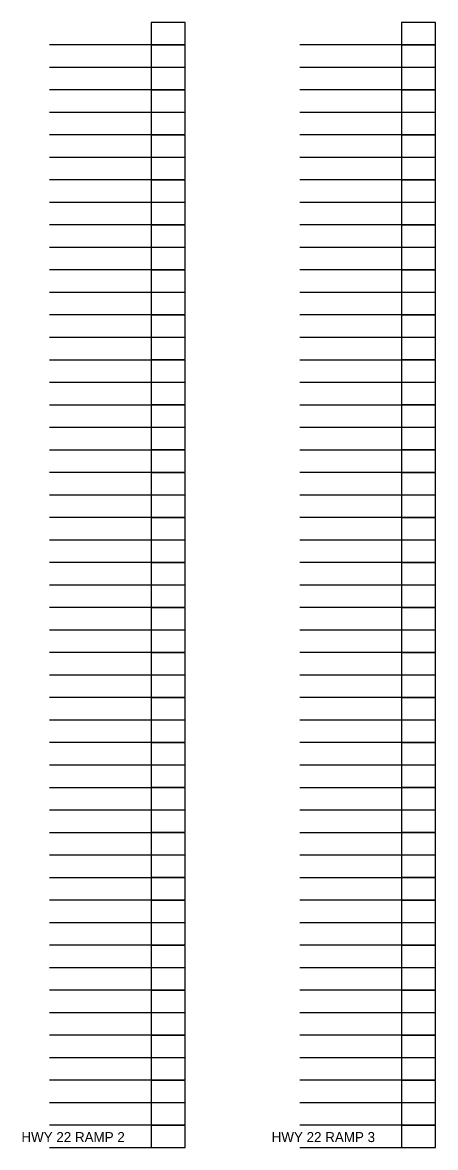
# Model space of a CAD drawing. Extents: x 625451 to 4181825, y 337941 to 441164.
# Drawn here: x 678612 to 686863, y 373673 to 396164 of the extents above; entities that cross this region are included whole.
import ezdxf

# ---------------------------------------------------------------- set-up
doc = ezdxf.new("R2010")
doc.units = 0
for name, color, linetype in [('PLOT_BDR-NOTUSED', 7, 'Continuous'), ('R_CX_LAYOUT-HWY 22-RAMP2', 7, 'Continuous'), ('R_CX_LAYOUT-HWY 22-RAMP3', 7, 'Continuous'), ('R_No Plot_SEG2_FR', 7, 'Continuous')]:
    doc.layers.add(name, color=color, linetype=linetype)

msp = doc.modelspace()

# ---------------------------------------------------------------- linework, layer by layer
at = {"layer": 'PLOT_BDR-NOTUSED'}
for points in [[(681863, 396164), (681183, 396164), (681183, 395724), (681863, 395724)], [(686863, 396164), (686183, 396164), (686183, 395724), (686863, 395724)], [(681863, 395714), (681183, 395714), (681183, 395274), (681863, 395274)], [(686863, 395714), (686183, 395714), (686183, 395274), (686863, 395274)], [(681863, 395264), (681183, 395264), (681183, 394824), (681863, 394824)], [(686863, 395264), (686183, 395264), (686183, 394824), (686863, 394824)], [(681863, 394814), (681183, 394814), (681183, 394374), (681863, 394374)], [(686863, 394814), (686183, 394814), (686183, 394374), (686863, 394374)], [(681863, 394364), (681183, 394364), (681183, 393924), (681863, 393924)], [(686863, 394364), (686183, 394364), (686183, 393924), (686863, 393924)], [(681863, 393914), (681183, 393914), (681183, 393474), (681863, 393474)], [(686863, 393914), (686183, 393914), (686183, 393474), (686863, 393474)], [(681863, 393464), (681183, 393464), (681183, 393024), (681863, 393024)], [(686863, 393464), (686183, 393464), (686183, 393024), (686863, 393024)], [(681863, 393014), (681183, 393014), (681183, 392574), (681863, 392574)], [(686863, 393014), (686183, 393014), (686183, 392574), (686863, 392574)], [(681863, 392564), (681183, 392564), (681183, 392124), (681863, 392124)], [(686863, 392564), (686183, 392564), (686183, 392124), (686863, 392124)], [(681863, 392114), (681183, 392114), (681183, 391674), (681863, 391674)], [(686863, 392114), (686183, 392114), (686183, 391674), (686863, 391674)], [(681863, 391664), (681183, 391664), (681183, 391224), (681863, 391224)], [(686863, 391664), (686183, 391664), (686183, 391224), (686863, 391224)], [(681863, 391214), (681183, 391214), (681183, 390774), (681863, 390774)], [(686863, 391214), (686183, 391214), (686183, 390774), (686863, 390774)], [(681863, 390764), (681183, 390764), (681183, 390324), (681863, 390324)], [(686863, 390764), (686183, 390764), (686183, 390324), (686863, 390324)], [(681863, 390314), (681183, 390314), (681183, 389874), (681863, 389874)], [(686863, 390314), (686183, 390314), (686183, 389874), (686863, 389874)], [(681863, 389864), (681183, 389864), (681183, 389424), (681863, 389424)], [(686863, 389864), (686183, 389864), (686183, 389424), (686863, 389424)], [(681863, 389414), (681183, 389414), (681183, 388974), (681863, 388974)], [(686863, 389414), (686183, 389414), (686183, 388974), (686863, 388974)], [(681863, 388964), (681183, 388964), (681183, 388524), (681863, 388524)], [(686863, 388964), (686183, 388964), (686183, 388524), (686863, 388524)], [(681863, 388514), (681183, 388514), (681183, 388074), (681863, 388074)], [(686863, 388514), (686183, 388514), (686183, 388074), (686863, 388074)], [(681863, 388064), (681183, 388064), (681183, 387624), (681863, 387624)], [(686863, 388064), (686183, 388064), (686183, 387624), (686863, 387624)], [(681863, 387614), (681183, 387614), (681183, 387174), (681863, 387174)], [(686863, 387614), (686183, 387614), (686183, 387174), (686863, 387174)], [(681863, 387164), (681183, 387164), (681183, 386724), (681863, 386724)], [(686863, 387164), (686183, 387164), (686183, 386724), (686863, 386724)], [(681863, 386714), (681183, 386714), (681183, 386274), (681863, 386274)], [(686863, 386714), (686183, 386714), (686183, 386274), (686863, 386274)], [(681863, 386264), (681183, 386264), (681183, 385824), (681863, 385824)], [(686863, 386264), (686183, 386264), (686183, 385824), (686863, 385824)], [(681863, 385814), (681183, 385814), (681183, 385374), (681863, 385374)], [(686863, 385814), (686183, 385814), (686183, 385374), (686863, 385374)], [(681863, 385364), (681183, 385364), (681183, 384924), (681863, 384924)], [(686863, 385364), (686183, 385364), (686183, 384924), (686863, 384924)], [(681863, 384914), (681183, 384914), (681183, 384474), (681863, 384474)], [(686863, 384914), (686183, 384914), (686183, 384474), (686863, 384474)], [(681863, 384464), (681183, 384464), (681183, 384024), (681863, 384024)], [(686863, 384464), (686183, 384464), (686183, 384024), (686863, 384024)], [(681863, 384014), (681183, 384014), (681183, 383574), (681863, 383574)], [(686863, 384014), (686183, 384014), (686183, 383574), (686863, 383574)], [(681863, 383564), (681183, 383564), (681183, 383124), (681863, 383124)], [(686863, 383564), (686183, 383564), (686183, 383124), (686863, 383124)], [(681863, 383114), (681183, 383114), (681183, 382674), (681863, 382674)], [(686863, 383114), (686183, 383114), (686183, 382674), (686863, 382674)], [(681863, 382664), (681183, 382664), (681183, 382224), (681863, 382224)], [(686863, 382664), (686183, 382664), (686183, 382224), (686863, 382224)], [(681863, 382214), (681183, 382214), (681183, 381774), (681863, 381774)], [(686863, 382214), (686183, 382214), (686183, 381774), (686863, 381774)], [(681863, 381764), (681183, 381764), (681183, 381324), (681863, 381324)], [(686863, 381764), (686183, 381764), (686183, 381324), (686863, 381324)], [(681863, 381314), (681183, 381314), (681183, 380874), (681863, 380874)], [(686863, 381314), (686183, 381314), (686183, 380874), (686863, 380874)], [(681863, 380864), (681183, 380864), (681183, 380424), (681863, 380424)], [(686863, 380864), (686183, 380864), (686183, 380424), (686863, 380424)], [(681863, 380414), (681183, 380414), (681183, 379974), (681863, 379974)], [(686863, 380414), (686183, 380414), (686183, 379974), (686863, 379974)], [(681863, 379964), (681183, 379964), (681183, 379524), (681863, 379524)], [(686863, 379964), (686183, 379964), (686183, 379524), (686863, 379524)], [(681863, 379514), (681183, 379514), (681183, 379074), (681863, 379074)], [(686863, 379514), (686183, 379514), (686183, 379074), (686863, 379074)], [(681863, 379064), (681183, 379064), (681183, 378624), (681863, 378624)], [(686863, 379064), (686183, 379064), (686183, 378624), (686863, 378624)], [(681863, 378614), (681183, 378614), (681183, 378174), (681863, 378174)], [(681863, 378164), (681183, 378164), (681183, 377724), (681863, 377724)]]:
    msp.add_lwpolyline(points, close=True, dxfattribs=at)
at = {"layer": 'R_CX_LAYOUT-HWY 22-RAMP2'}
for p, q in [((679152, 395723), (681251, 395723)), ((679152, 395273), (681251, 395273)), ((679152, 394823), (681251, 394823)), ((679152, 394373), (681251, 394373)), ((679152, 393923), (681251, 393923)), ((679152, 393473), (681251, 393473)), ((679152, 393023), (681251, 393023)), ((679152, 392573), (681251, 392573)), ((679152, 392123), (681251, 392123)), ((679152, 391673), (681251, 391673)), ((679152, 391223), (681251, 391223)), ((679152, 390773), (681251, 390773)), ((679152, 390323), (681251, 390323)), ((679152, 389873), (681251, 389873)), ((679152, 389423), (681251, 389423)), ((679152, 388973), (681251, 388973)), ((679152, 388523), (681251, 388523)), ((679152, 388073), (681251, 388073)), ((679152, 387623), (681251, 387623)), ((679152, 387173), (681251, 387173)), ((679152, 386723), (681251, 386723)), ((679152, 386273), (681251, 386273)), ((679152, 385823), (681251, 385823)), ((679152, 385373), (681251, 385373)), ((679152, 384923), (681251, 384923)), ((679152, 384473), (681251, 384473)), ((679152, 384023), (681251, 384023)), ((679152, 383573), (681251, 383573)), ((679152, 383123), (681251, 383123)), ((679152, 382673), (681251, 382673)), ((679152, 382223), (681251, 382223)), ((679152, 381773), (681251, 381773)), ((679152, 381323), (681251, 381323)), ((679152, 380873), (681251, 380873)), ((679152, 380423), (681251, 380423)), ((679152, 379973), (681251, 379973)), ((679152, 379523), (681251, 379523)), ((679152, 379073), (681251, 379073)), ((679152, 378623), (681251, 378623)), ((679152, 378173), (681251, 378173)), ((679152, 377723), (681251, 377723)), ((679152, 377273), (681251, 377273)), ((679152, 376823), (681251, 376823)), ((679152, 376373), (681251, 376373)), ((679152, 375923), (681251, 375923)), ((679152, 375473), (681251, 375473)), ((679152, 375023), (681251, 375023)), ((679152, 374573), (681251, 374573)), ((679152, 374123), (681251, 374123)), ((679152, 373673), (681251, 373673))]:
    msp.add_line(p, q, dxfattribs=at)
at = {"layer": 'R_CX_LAYOUT-HWY 22-RAMP3'}
for p, q in [((684152, 395723), (686251, 395723)), ((684152, 395273), (686251, 395273)), ((684152, 394823), (686251, 394823)), ((684152, 394373), (686251, 394373)), ((684152, 393923), (686251, 393923)), ((684152, 393473), (686251, 393473)), ((684152, 393023), (686251, 393023)), ((684152, 392573), (686251, 392573)), ((684152, 392123), (686251, 392123)), ((684152, 391673), (686251, 391673)), ((684152, 391223), (686251, 391223)), ((684152, 390773), (686251, 390773)), ((684152, 390323), (686251, 390323)), ((684152, 389873), (686251, 389873)), ((684152, 389423), (686251, 389423)), ((684152, 388973), (686251, 388973)), ((684152, 388523), (686251, 388523)), ((684152, 388073), (686251, 388073)), ((684152, 387623), (686251, 387623)), ((684152, 387173), (686251, 387173)), ((684152, 386723), (686251, 386723)), ((684152, 386273), (686251, 386273)), ((684152, 385823), (686251, 385823)), ((684152, 385373), (686251, 385373)), ((684152, 384923), (686251, 384923)), ((684152, 384473), (686251, 384473)), ((684152, 384023), (686251, 384023)), ((684152, 383573), (686251, 383573)), ((684152, 383123), (686251, 383123)), ((684152, 382673), (686251, 382673)), ((684152, 382223), (686251, 382223)), ((684152, 381773), (686251, 381773)), ((684152, 381323), (686251, 381323)), ((684152, 380873), (686251, 380873)), ((684152, 380423), (686251, 380423)), ((684152, 379973), (686251, 379973)), ((684152, 379523), (686251, 379523)), ((684152, 379073), (686251, 379073)), ((684152, 378623), (686251, 378623)), ((684152, 378173), (686251, 378173)), ((684152, 377723), (686251, 377723)), ((684152, 377273), (686251, 377273)), ((684152, 376823), (686251, 376823)), ((684152, 376373), (686251, 376373)), ((684152, 375923), (686251, 375923)), ((684152, 375473), (686251, 375473)), ((684152, 375023), (686251, 375023)), ((684152, 374573), (686251, 374573)), ((684152, 374123), (686251, 374123)), ((684152, 373673), (686251, 373673))]:
    msp.add_line(p, q, dxfattribs=at)
at = {"layer": 'R_No Plot_SEG2_FR'}
for points in [[(686863, 378614), (686183, 378614), (686183, 378174), (686863, 378174)], [(686863, 378164), (686183, 378164), (686183, 377724), (686863, 377724)], [(681863, 377714), (681183, 377714), (681183, 377274), (681863, 377274)], [(686863, 377714), (686183, 377714), (686183, 377274), (686863, 377274)], [(681863, 377264), (681183, 377264), (681183, 376824), (681863, 376824)], [(686863, 377264), (686183, 377264), (686183, 376824), (686863, 376824)], [(681863, 376814), (681183, 376814), (681183, 376374), (681863, 376374)], [(686863, 376814), (686183, 376814), (686183, 376374), (686863, 376374)], [(681863, 376364), (681183, 376364), (681183, 375924), (681863, 375924)], [(686863, 376364), (686183, 376364), (686183, 375924), (686863, 375924)], [(681863, 375914), (681183, 375914), (681183, 375474), (681863, 375474)], [(686863, 375914), (686183, 375914), (686183, 375474), (686863, 375474)], [(681863, 375464), (681183, 375464), (681183, 375024), (681863, 375024)], [(686863, 375464), (686183, 375464), (686183, 375024), (686863, 375024)], [(681863, 375014), (681183, 375014), (681183, 374574), (681863, 374574)], [(686863, 375014), (686183, 375014), (686183, 374574), (686863, 374574)], [(681863, 374564), (681183, 374564), (681183, 374124), (681863, 374124)], [(686863, 374564), (686183, 374564), (686183, 374124), (686863, 374124)], [(681863, 374114), (681183, 374114), (681183, 373674), (681863, 373674)], [(686863, 374114), (686183, 374114), (686183, 373674), (686863, 373674)]]:
    msp.add_lwpolyline(points, close=True, dxfattribs=at)

# ---------------------------------------------------------------- texts
at = {"layer": 'R_CX_LAYOUT-HWY 22-RAMP2'}
msp.add_text('HWY 22 RAMP 2', height=200, dxfattribs=at).set_placement((678590, 373781))
at = {"layer": 'R_CX_LAYOUT-HWY 22-RAMP3'}
msp.add_text('HWY 22 RAMP 3', height=200, dxfattribs=at).set_placement((683590, 373781))

doc.saveas('drawing.dxf')
